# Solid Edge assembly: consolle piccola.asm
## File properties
Title: Consolle Fuji
Author: i.fialdini
Template: iso assembly.asm
Last saved by: a.ravenna
Revision: 5
Application: Solid Edge
Tipo di contenuto documento: 1
Document Number: 6005
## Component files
consolle piccola.par
consolle piccola_0.par
consolle piccola_1.par
consolle piccola_2.par
consolle piccola_3.par
consolle piccola_4.par
consolle piccola_5.par
consolle piccola_6.par
consolle piccola_7.par
consolle piccola_8.par
consolle piccola_9.par
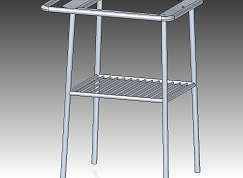
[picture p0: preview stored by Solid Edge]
